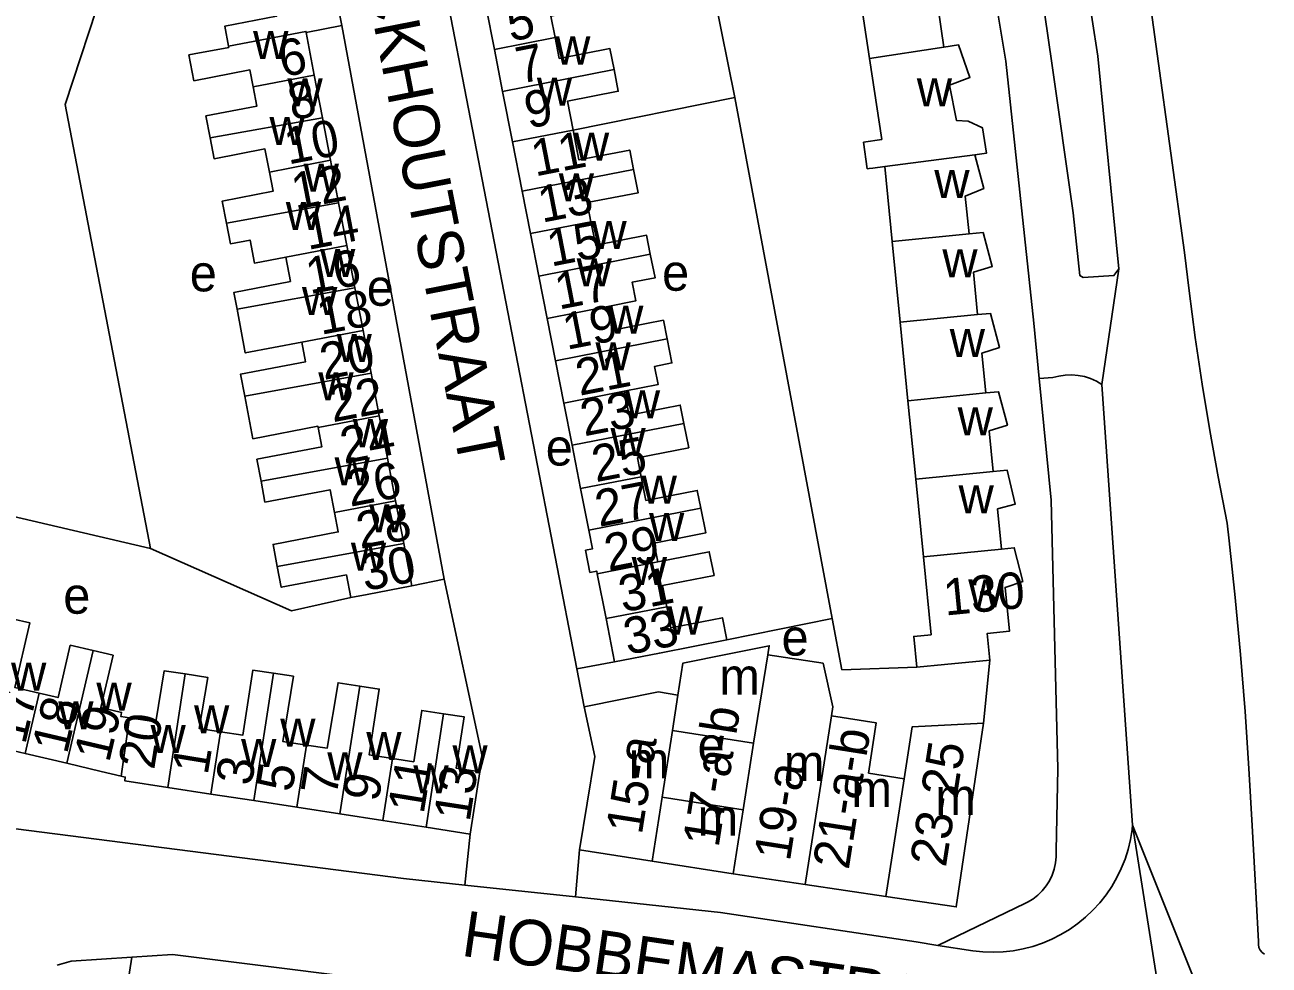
# Model space of a CAD drawing. Extents: x 161775 to 163181, y 382878 to 383925.
# Drawn here: x 163043.8 to 163180.3, y 383281.3 to 383384.3 of the extents above; entities that cross this region are included whole.
import ezdxf

# ---------------------------------------------------------------- set-up
doc = ezdxf.new("R2010")
doc.units = 0
for name, color, linetype in [('BLT_Basislijn', 7, 'Continuous'), ('BLT_Bebouwing', 7, 'Continuous'), ('BLT_Centroide', 7, 'Continuous'), ('BLT_Huisnummer', 7, 'Continuous'), ('BLT_Huisnummer_ tussenligend', 7, 'Continuous'), ('BLT_Huisnummer_reeks', 7, 'Continuous'), ('BLT_Onderverdeling_panden', 7, 'Continuous'), ('BLT_Straatnaam', 7, 'Continuous'), ('BLT_Vlakafsluiter', 7, 'Continuous')]:
    doc.layers.add(name, color=color, linetype=linetype)

msp = doc.modelspace()

# ---------------------------------------------------------------- linework, layer by layer
at = {"layer": 'BLT_Basislijn'}
for p, q in [((163110.18, 383433.27), (163121.68, 383376.37)), ((163082.32, 383427.73), (163104.37, 383313.73)), ((163149, 383394.86), (163151.42, 383380.32)), ((163078.59, 383384.23), (163089.82, 383323.55)), ((163163.81, 383357.58), (163161.48, 383380.88)), ((163103.95, 383372.78), (163121.68, 383376.37)), ((163121.68, 383376.37), (163132.37, 383319.24)), ((163156.54, 383345.65), (163155.07, 383345.56)), ((163155.07, 383345.56), (163156.36, 383332.22)), ((163165.3, 383296.62), (163161.94, 383344.9)), ((163089.82, 383323.55), (163086.27, 383322.82)), ((163120.8, 383316.91), (163132.37, 383319.24)), ((163132.37, 383319.24), (163133.41, 383313.63)), ((163108.51, 383314.49), (163104.37, 383313.73)), ((163104.37, 383313.73), (163105.15, 383309.56)), ((163141.63, 383313.91), (163133.41, 383313.63)), ((163149.65, 383314.7), (163148.97, 383307.79)), ((163178.41, 383296.57), (163178.86, 383288.62)), ((163092.67, 383295.63), (163092.07, 383290.04)), ((163104.65, 383293.91), (163104.21, 383288.74)), ((163104.21, 383288.74), (163120.1, 383287.03)), ((163153.56, 383288.05), (163143.96, 383283.43)), ((163178.86, 383288.62), (163179.11, 383283.84)), ((163141.56, 383283.8), (163120.1, 383287.03)), ((163141.56, 383283.8), (163143.96, 383283.43)), ((163055.58, 383282.14), (163060.03, 383282.43)), ((163060.03, 383282.43), (163089.53, 383278.73)), ((163143.96, 383283.43), (163147.79, 383282.83)), ((163051.55, 383257.31), (163055.58, 383282.14))]:
    msp.add_line(p, q, dxfattribs=at)
for points in [[(163152.82, 383431.76), (163159.62, 383392.99), (163161.48, 383380.88)], [(163147.92, 383430.75), (163152.54, 383407.16), (163156.45, 383380.13)], [(163166.59, 383400.1), (163166.48, 383392.07), (163171, 383359.35)], [(163051.6, 383393.51), (163052.53, 383388.64), (163048.26, 383375.6), (163057.6, 383326.93)], [(163151.42, 383380.32), (163154.49, 383351.61), (163155.07, 383345.56)], [(163156.45, 383380.13), (163158.78, 383363.73), (163159.52, 383356.83), (163159.9, 383356.64), (163163.25, 383356.83), (163163.81, 383357.58)], [(163175.66, 383329.71), (163174.67, 383334.77), (163173.76, 383339.85), (163172.92, 383344.95), (163172.17, 383350.05), (163171.49, 383355.17), (163171, 383359.35)], [(163161.94, 383344.9), (163161.34, 383345.26), (163160.69, 383345.55), (163160.02, 383345.76), (163159.33, 383345.9), (163158.63, 383345.95), (163157.92, 383345.93), (163157.22, 383345.83), (163156.54, 383345.65)], [(163057.6, 383326.93), (163007.4, 383338.67)], [(163156.36, 383332.22), (163157.1, 383302.77), (163156.91, 383293.83)], [(163178.41, 383296.57), (163178.06, 383302.82), (163177.64, 383309.07), (163177.13, 383315.32), (163176.55, 383321.55), (163175.88, 383327.78), (163175.66, 383329.71)], [(163079.57, 383321.54), (163073.08, 383320.11), (163057.6, 383326.93)], [(163089.82, 383323.55), (163094.01, 383303.97), (163093.72, 383302.45)], [(163041.43, 383296.38), (163085.37, 383290.76), (163092.07, 383290.04)], [(163147.79, 383282.83), (163148.89, 383282.71), (163150, 383282.67), (163151.11, 383282.72), (163152.21, 383282.84), (163153.3, 383283.04), (163154.38, 383283.32), (163155.43, 383283.68), (163156.45, 383284.11), (163157.44, 383284.61), (163158.39, 383285.18), (163159.3, 383285.82), (163160.15, 383286.53), (163160.96, 383287.29), (163161.71, 383288.11), (163162.39, 383288.98), (163163.02, 383289.9), (163163.57, 383290.86), (163164.06, 383291.86), (163164.47, 383292.89), (163164.8, 383293.95), (163165.06, 383295.03), (163165.24, 383296.12), (163165.3, 383296.62)], [(163156.91, 383293.83), (163156.93, 383293.14), (163156.86, 383292.46), (163156.72, 383291.79), (163156.49, 383291.14), (163156.2, 383290.52), (163155.83, 383289.94), (163155.4, 383289.41), (163154.91, 383288.93), (163154.37, 383288.51), (163153.78, 383288.16), (163153.56, 383288.05)], [(163179.11, 383283.84), (163179.1, 383283.52), (163179.16, 383283.2), (163179.3, 383282.91), (163179.5, 383282.66), (163179.76, 383282.47), (163179.77, 383282.46)]]:
    msp.add_lwpolyline(points, dxfattribs=at)
at = {"layer": 'BLT_Bebouwing'}
for p, q in [((163078.59, 383384.23), (163077.68, 383389.01)), ((163135.14, 383389.21), (163136.45, 383380.64)), ((163095.32, 383381.62), (163094.41, 383386.21)), ((163074.68, 383383.48), (163078.59, 383384.23)), ((163075.57, 383378.81), (163074.68, 383383.48)), ((163096.22, 383377.03), (163095.32, 383381.62)), ((163136.45, 383380.64), (163137.81, 383371.77)), ((163076.46, 383374.14), (163075.57, 383378.81)), ((163097.31, 383371.48), (163096.22, 383377.03)), ((163077.35, 383369.47), (163076.46, 383374.14)), ((163098.37, 383366.08), (163097.31, 383371.48)), ((163137.81, 383371.77), (163135.81, 383371.46)), ((163078.24, 383364.81), (163077.35, 383369.47)), ((163138.14, 383368.81), (163138.95, 383360.57)), ((163099.28, 383361.44), (163098.37, 383366.08)), ((163079.14, 383360.14), (163078.24, 383364.81)), ((163100.2, 383356.79), (163099.28, 383361.44)), ((163080.03, 383355.48), (163079.14, 383360.14)), ((163138.95, 383360.57), (163139.83, 383351.73)), ((163072.44, 383358.86), (163072.96, 383356.18)), ((163101.11, 383352.15), (163100.2, 383356.79)), ((163080.92, 383350.81), (163080.03, 383355.48)), ((163102.02, 383347.5), (163101.11, 383352.15)), ((163139.83, 383351.73), (163140.67, 383343.12)), ((163081.81, 383346.14), (163080.92, 383350.81)), ((163102.93, 383342.86), (163102.02, 383347.5)), ((163082.7, 383341.48), (163081.81, 383346.14)), ((163103.84, 383338.24), (163102.93, 383342.86)), ((163140.67, 383343.12), (163141.52, 383334.54)), ((163083.6, 383336.81), (163082.7, 383341.48)), ((163104.77, 383333.49), (163103.84, 383338.24)), ((163084.49, 383332.15), (163083.6, 383336.81)), ((163141.52, 383334.54), (163142.36, 383326.02)), ((163105.67, 383328.92), (163104.77, 383333.49)), ((163085.38, 383327.48), (163084.49, 383332.15)), ((163086.27, 383322.82), (163085.38, 383327.48)), ((163107.58, 383319.24), (163106.61, 383324.16)), ((163108.51, 383314.49), (163107.58, 383319.24)), ((163125.31, 383315.29), (163131.36, 383314.35)), ((163114.84, 383306.98), (163113.71, 383299.66)), ((163123.74, 383305.6), (163114.84, 383306.98)), ((163043.86, 383304.46), (163039.27, 383305.54)), ((163122.6, 383298.27), (163123.74, 383305.6)), ((163048.44, 383303.39), (163043.86, 383304.46)), ((163052.21, 383302.5), (163048.44, 383303.39)), ((163054.39, 383301.99), (163052.21, 383302.5)), ((163093.72, 383302.45), (163092.67, 383295.63)), ((163136.33, 383302.3), (163140.26, 383301.68)), ((163064.23, 383300.02), (163059.5, 383300.74)), ((163068.95, 383299.29), (163064.23, 383300.02)), ((163073.67, 383298.56), (163068.95, 383299.29)), ((163078.39, 383297.83), (163073.67, 383298.56)), ((163113.71, 383299.66), (163122.6, 383298.27)), ((163083.11, 383297.1), (163078.39, 383297.83)), ((163087.83, 383296.37), (163083.11, 383297.1)), ((163092.67, 383295.63), (163087.83, 383296.37)), ((163112.61, 383292.66), (163104.65, 383293.91)), ((163121.5, 383291.27), (163112.61, 383292.66)), ((163129.39, 383290.11), (163121.5, 383291.27)), ((163138.24, 383288.79), (163129.39, 383290.11))]:
    msp.add_line(p, q, dxfattribs=at)
for points in [[(163143.35, 383390.46), (163144.82, 383390.69), (163146.1, 383386.97), (163143.97, 383386.16), (163144.62, 383381.89)], [(163101.98, 383382.93), (163101.53, 383385.28), (163107.1, 383386.36), (163106.66, 383388.61)], [(163070.97, 383387.73), (163071.45, 383385.26), (163065.76, 383384.17), (163066.18, 383381.98)], [(163066.18, 383381.98), (163066.2, 383381.85), (163062.4, 383381.13), (163061.83, 383381.02), (163062.38, 383378.2), (163068.52, 383379.37), (163068.87, 383377.53)], [(163108.44, 383379.43), (163107.99, 383381.72), (163102.43, 383380.64), (163101.98, 383382.93)], [(163144.62, 383381.89), (163146.21, 383382.14), (163147.46, 383378.53), (163145.23, 383377.72), (163146.01, 383373.83), (163147.29, 383373.75), (163148.85, 383373.02), (163149.28, 383370.25), (163148.01, 383370.08)], [(163103.95, 383372.78), (163103.33, 383375.95), (163108.9, 383377.04), (163108.44, 383379.43)], [(163068.87, 383377.53), (163069.28, 383375.41), (163063.7, 383374.34), (163064.16, 383371.92)], [(163110.58, 383368.48), (163110.16, 383370.6), (163104.59, 383369.52), (163103.95, 383372.78)], [(163064.16, 383371.92), (163064.59, 383369.65), (163070.17, 383370.72), (163070.66, 383368.19)], [(163135.81, 383371.46), (163136.2, 383368.55), (163136.4, 383368.57), (163136.82, 383368.61), (163138.14, 383368.81)], [(163148.01, 383370.08), (163149, 383366.38), (163146.96, 383365.56), (163147.37, 383361.4)], [(163070.66, 383368.19), (163071.06, 383366.08), (163065.48, 383365.01), (163065.94, 383362.59)], [(163105.9, 383362.74), (163105.51, 383364.83), (163111.09, 383365.92), (163110.58, 383368.48)], [(163112.42, 383359.2), (163112.02, 383361.26), (163106.43, 383360.17), (163105.9, 383362.74)], [(163065.94, 383362.59), (163066.38, 383360.32), (163068.54, 383360.73), (163069.02, 383358.21), (163072.44, 383358.86)], [(163147.37, 383361.4), (163148.9, 383361.55), (163149.92, 383357.85), (163147.85, 383357.21), (163148.31, 383352.56)], [(163107.75, 383353.45), (163110.83, 383354.06), (163110.43, 383356.1), (163112.94, 383356.58), (163112.42, 383359.2)], [(163072.96, 383356.18), (163066.76, 383354.99), (163067.11, 383353.14)], [(163067.11, 383353.14), (163068.01, 383348.36), (163074.22, 383349.53)], [(163114.27, 383349.91), (163113.86, 383351.94), (163108.26, 383350.85), (163107.75, 383353.45)], [(163148.31, 383352.56), (163149.71, 383352.7), (163150.69, 383348.96), (163148.77, 383348.33), (163149.2, 383343.97)], [(163074.22, 383349.53), (163074.63, 383347.4), (163067.49, 383346.04), (163067.95, 383343.62)], [(163109.56, 383344.16), (163113.27, 383344.89), (163112.88, 383346.89), (163114.79, 383347.27), (163114.27, 383349.91)], [(163067.95, 383343.62), (163068.85, 383338.95), (163075.98, 383340.32), (163076.01, 383340.2)], [(163116.11, 383340.62), (163115.71, 383342.64), (163110.09, 383341.54), (163109.56, 383344.16)], [(163149.2, 383343.97), (163150.6, 383344.1), (163151.57, 383340.44), (163149.59, 383339.82), (163150.02, 383335.38)], [(163076.01, 383340.2), (163076.41, 383338.07), (163069.28, 383336.7), (163069.74, 383334.29)], [(163111.42, 383334.78), (163111.01, 383336.86), (163116.64, 383337.96), (163116.11, 383340.62)], [(163150.02, 383335.38), (163151.54, 383335.53), (163152.44, 383331.79), (163150.49, 383331.26), (163150.93, 383326.87)], [(163069.74, 383334.29), (163070.17, 383332.01), (163077.31, 383333.37), (163077.79, 383330.87)], [(163117.95, 383331.34), (163117.56, 383333.3), (163111.93, 383332.2), (163111.42, 383334.78)], [(163113.23, 383325.46), (163112.85, 383327.52), (163118.49, 383328.63), (163117.95, 383331.34)], [(163077.79, 383330.87), (163078.2, 383328.74), (163071.06, 383327.37), (163071.52, 383324.95)], [(163106.61, 383324.16), (163106.55, 383324.46), (163105.79, 383324.31), (163105.32, 383326.74), (163106.07, 383326.89), (163105.67, 383328.92)], [(163114.22, 383320.54), (163113.76, 383322.88), (163119.41, 383323.98), (163118.89, 383326.57), (163113.23, 383325.46)], [(163142.36, 383326.02), (163143.2, 383317.48), (163141.3, 383317.29), (163141.63, 383313.91)], [(163150.93, 383326.87), (163152.32, 383327.01), (163153.26, 383323.31), (163151.32, 383322.66), (163151.79, 383317.86), (163149.37, 383317.62), (163149.65, 383314.7)], [(163071.52, 383324.95), (163071.95, 383322.68), (163079.09, 383324.04), (163079.57, 383321.54)], [(163079.57, 383321.54), (163081.36, 383321.88), (163086.27, 383322.82)], [(163120.8, 383316.91), (163120.33, 383319.33), (163114.67, 383318.22), (163114.22, 383320.54)], [(163045.4, 383311.07), (163042.74, 383311.7), (163044.39, 383318.77), (163042.45, 383319.23)], [(163051.34, 383315.73), (163048.82, 383316.32), (163047.48, 383310.59), (163045.4, 383311.07)], [(163120.8, 383316.91), (163113.42, 383315.46), (163108.51, 383314.49)], [(163115.45, 383310.87), (163115.99, 383314.36), (163120.89, 383315.35), (163125.47, 383316.27), (163125.31, 383315.29)], [(163055.33, 383308.37), (163054.36, 383308.52), (163054.44, 383308.96), (163052.17, 383309.49), (163053.51, 383315.22), (163051.34, 383315.73)], [(163055.33, 383308.37), (163058.19, 383307.92), (163059.12, 383313.53), (163061.41, 383313.18)], [(163065.29, 383306.83), (163067.74, 383306.45), (163068.85, 383313.6), (163071.11, 383313.26)], [(163131.36, 383314.35), (163132.43, 383309.56), (163132.28, 383308.58)], [(163141.63, 383313.91), (163144.68, 383314.21), (163149.65, 383314.7)], [(163061.41, 383313.18), (163063.89, 383312.8), (163062.96, 383307.19), (163065.29, 383306.83)], [(163071.11, 383313.26), (163073.29, 383312.92), (163072.11, 383305.78), (163074.73, 383305.37)], [(163074.73, 383305.37), (163077, 383305.05), (163078.19, 383312.22), (163080.56, 383311.85)], [(163080.56, 383311.85), (163082.7, 383311.52), (163081.59, 383304.32), (163084.17, 383303.92)], [(163105.15, 383309.56), (163113.31, 383311.2), (163115.45, 383310.87)], [(163104.65, 383293.91), (163106.35, 383304.12), (163105.15, 383309.56)], [(163084.17, 383303.92), (163086.48, 383303.56), (163087.35, 383309.18), (163089.75, 383308.81)], [(163089.75, 383308.81), (163092.02, 383308.46), (163091.15, 383302.84), (163093.72, 383302.45)], [(163132.28, 383308.58), (163137.2, 383307.81), (163136.33, 383302.3)], [(163148.97, 383307.79), (163145.96, 383287.64), (163138.24, 383288.79)], [(163140.26, 383301.68), (163141.15, 383307.39), (163148.97, 383307.79)], [(163059.5, 383300.74), (163054.79, 383301.47), (163054.85, 383301.88), (163054.39, 383301.99)]]:
    msp.add_lwpolyline(points, dxfattribs=at)
at = {"layer": 'BLT_Onderverdeling_panden'}
for p, q in [((163144.62, 383381.89), (163136.45, 383380.64)), ((163075.57, 383378.81), (163068.87, 383377.53)), ((163076.46, 383374.14), (163064.16, 383371.92)), ((163077.35, 383369.47), (163070.66, 383368.19)), ((163148.01, 383370.08), (163138.14, 383368.81)), ((163078.24, 383364.81), (163065.94, 383362.59)), ((163105.9, 383362.74), (163099.28, 383361.44)), ((163147.37, 383361.4), (163138.95, 383360.57)), ((163079.14, 383360.14), (163072.44, 383358.86)), ((163112.42, 383359.2), (163100.2, 383356.79)), ((163080.03, 383355.48), (163067.11, 383353.14)), ((163107.75, 383353.45), (163101.11, 383352.15)), ((163148.31, 383352.56), (163139.83, 383351.73)), ((163080.92, 383350.81), (163074.22, 383349.53)), ((163114.27, 383349.91), (163102.02, 383347.5)), ((163081.81, 383346.14), (163067.95, 383343.62)), ((163109.56, 383344.16), (163102.93, 383342.86)), ((163149.2, 383343.97), (163140.67, 383343.12)), ((163082.7, 383341.48), (163076.01, 383340.2)), ((163116.11, 383340.62), (163103.84, 383338.24)), ((163083.6, 383336.81), (163069.74, 383334.29)), ((163150.02, 383335.38), (163141.52, 383334.54)), ((163111.42, 383334.78), (163104.77, 383333.49)), ((163084.49, 383332.15), (163077.79, 383330.87)), ((163117.95, 383331.34), (163105.67, 383328.92)), ((163085.38, 383327.48), (163071.52, 383324.95)), ((163150.93, 383326.87), (163142.36, 383326.02)), ((163113.23, 383325.46), (163106.61, 383324.16)), ((163114.22, 383320.54), (163107.58, 383319.24)), ((163048.44, 383303.39), (163051.34, 383315.73)), ((163123.74, 383305.6), (163125.31, 383315.29)), ((163059.5, 383300.74), (163061.41, 383313.18)), ((163068.95, 383299.29), (163071.11, 383313.26)), ((163043.86, 383304.46), (163045.4, 383311.07)), ((163078.39, 383297.83), (163080.56, 383311.85)), ((163115.45, 383310.87), (163114.84, 383306.98)), ((163054.39, 383301.99), (163055.33, 383308.37)), ((163087.83, 383296.37), (163089.75, 383308.81)), ((163132.28, 383308.58), (163129.39, 383290.11)), ((163064.23, 383300.02), (163065.29, 383306.83)), ((163073.67, 383298.56), (163074.73, 383305.37)), ((163083.11, 383297.1), (163084.17, 383303.92)), ((163140.26, 383301.68), (163138.24, 383288.79)), ((163113.71, 383299.66), (163112.61, 383292.66)), ((163122.6, 383298.27), (163121.5, 383291.27))]:
    msp.add_line(p, q, dxfattribs=at)
for points in [[(163066.18, 383381.98), (163074.66, 383383.6), (163074.68, 383383.48)], [(163101.98, 383382.93), (163095.32, 383381.62)], [(163108.44, 383379.43), (163096.22, 383377.03)], [(163103.95, 383372.78), (163097.31, 383371.48)], [(163110.58, 383368.48), (163098.37, 383366.08)]]:
    msp.add_lwpolyline(points, dxfattribs=at)
at = {"layer": 'BLT_Vlakafsluiter'}
for p, q in [((163161.94, 383344.9), (163163.81, 383357.58)), ((163180.27, 383259.17), (163165.3, 383296.62)), ((163165.3, 383296.62), (163171.67, 383256.23)), ((163092.07, 383290.04), (163104.21, 383288.74))]:
    msp.add_line(p, q, dxfattribs=at)
msp.add_lwpolyline([(163047.4, 383281.27), (163048.91, 383281.71), (163055.58, 383282.14)], dxfattribs=at)

# ---------------------------------------------------------------- texts
at = {"layer": 'BLT_Centroide'}
for s, p in [('w', (163068.87, 383380.56)), ('w', (163101.98, 383379.97)), ('w', (163072.63, 383375.38)), ('w', (163099.98, 383375.47)), ('w', (163141.64, 383375.39)), ('w', (163070.66, 383371.16)), ('w', (163104.05, 383369.44)), ('w', (163074.41, 383366.03)), ('w', (163143.56, 383365.34)), ('w', (163102.38, 383364.97)), ('w', (163072.45, 383361.84)), ('w', (163105.96, 383359.75)), ('w', (163076.21, 383356.69)), ('w', (163104.34, 383355.66)), ('w', (163144.44, 383356.66)), ('e', (163061.92, 383355.11)), ('e', (163113.71, 383355.18)), ('e', (163081.33, 383353.53)), ('w', (163074.23, 383352.5)), ('w', (163107.8, 383350.47)), ('w', (163078.02, 383347.38)), ('w', (163145.25, 383347.91)), ('w', (163106.41, 383346.44)), ('w', (163076.02, 383343.16)), ('w', (163109.63, 383341.19)), ('w', (163146.12, 383339.33)), ('w', (163079.8, 383338.03)), ('w', (163108.05, 383337.06)), ('e', (163100.95, 383336.02)), ('w', (163077.8, 383333.84)), ('w', (163111.47, 383331.84)), ('w', (163146.22, 383330.78)), ('w', (163081.6, 383328.69)), ('w', (163112.28, 383327.75)), ('w', (163079.59, 383324.5)), ('w', (163110.38, 383322.91)), ('w', (163147.28, 383320.48)), ('e', (163048.05, 383319.78)), ('w', (163114.3, 383317.5)), ('e', (163126.81, 383315.19)), ('w', (163042.33, 383311.33)), ('m', (163119.98, 383310.91)), ('w', (163051.69, 383309.14)), ('w', (163047.5, 383307.09)), ('w', (163062.39, 383306.67)), ('w', (163071.84, 383305.2)), ('w', (163057.62, 383304.52)), ('w', (163081.28, 383303.75)), ('w', (163067.55, 383302.98)), ('w', (163090.72, 383302.3)), ('e', (163117.6, 383303.37)), ('w', (163077, 383301.53)), ('m', (163110.05, 383301.72)), ('m', (163127.06, 383301.44)), ('w', (163086.44, 383300.08)), ('m', (163134.47, 383298.58)), ('m', (163143.66, 383297.73)), ('m', (163117.6, 383295.47))]:
    msp.add_text(s, height=4, dxfattribs=at).set_placement(p)
at = {"layer": 'BLT_Huisnummer'}
for s, rotation, p in [('5', 11.0211, (163097.08, 383382.48)), ('6', 10.8189, (163072.08, 383378.57)), ('9', 11.0211, (163099.05, 383372.94)), ('10', 10.8189, (163072.72, 383369)), ('13', 11.0227, (163100.54, 383362.62)), ('14', 10.8189, (163074.87, 383359.64)), ('17', 11.0144, (163102.39, 383353.1)), ('18', 10.8189, (163076.3, 383350.33)), ('21', 11.0144, (163104.66, 383343.66)), ('22', 10.8205, (163077.6, 383340.75)), ('25', 11.0144, (163106.44, 383334.18)), ('26', 10.8173, (163079.51, 383331.49)), ('30', 10.8132, (163081.11, 383322.25)), ('33', 11.1144, (163109.92, 383315.26)), ('17', 76.847, (163043.87, 383305.35)), ('19', 76.8587, (163053.08, 383303.36)), ('20', 80.738, (163058.01, 383302.6)), ('1', 80.7356, (163063.88, 383302.01)), ('5', 80.7343, (163073.14, 383300.13)), ('13', 81.2381, (163092.61, 383296.88)), ('9', 80.7343, (163082.61, 383299.06))]:
    msp.add_text(s, height=4, rotation=rotation, dxfattribs=at).set_placement(p)
at = {"layer": 'BLT_Huisnummer_ tussenligend'}
for s, rotation, p in [('7', 11.0211, (163098.11, 383377.85)), ('8', 10.8189, (163073.12, 383373.84)), ('11', 11.0211, (163099.79, 383367.69)), ('12', 10.8189, (163073.49, 383364.05)), ('15', 11.0227, (163101.53, 383357.81)), ('16', 10.8189, (163075.08, 383354.78)), ('19', 11.0144, (163103.25, 383348.69)), ('20', 10.8189, (163076.61, 383345.39)), ('23', 11.0144, (163105.17, 383339.21)), ('24', 10.8205, (163078.84, 383336.19)), ('27', 11.0144, (163106.8, 383329.28)), ('28', 10.8173, (163080.61, 383326.88)), ('29', 11.0211, (163107.82, 383324.46)), ('31', 11.0211, (163109.39, 383319.91)), ('18', 76.8587, (163048.46, 383304.3)), ('3', 80.7343, (163068.69, 383300.82)), ('7', 80.7343, (163078, 383299.69)), ('11', 80.7347, (163087.56, 383297.74))]:
    msp.add_text(s, height=4, rotation=rotation, dxfattribs=at).set_placement(p)
at = {"layer": 'BLT_Huisnummer_reeks'}
for s, rotation, p in [('130', 5.6365, (163144.75, 383319.57)), ('17-a-b', 81.1001, (163119.9, 383294.06)), ('21-a-b', 81.1035, (163134.17, 383291.64)), ('15-a', 81.1014, (163111.49, 383295.47)), ('23-25', 81.1004, (163144.82, 383291.91)), ('19-a', 81.1031, (163127.72, 383292.55))]:
    msp.add_text(s, height=4, rotation=rotation, dxfattribs=at).set_placement(p)
at = {"layer": 'BLT_Straatnaam'}
for s, rotation, p in [('EECKHOUTSTRAAT', 281.0751, (163079.43, 383397.91)), ('HOBBEMASTRAAT', 351.8032, (163091.58, 383282.31))]:
    msp.add_text(s, height=5, rotation=rotation, dxfattribs=at).set_placement(p)

doc.saveas('drawing.dxf')
